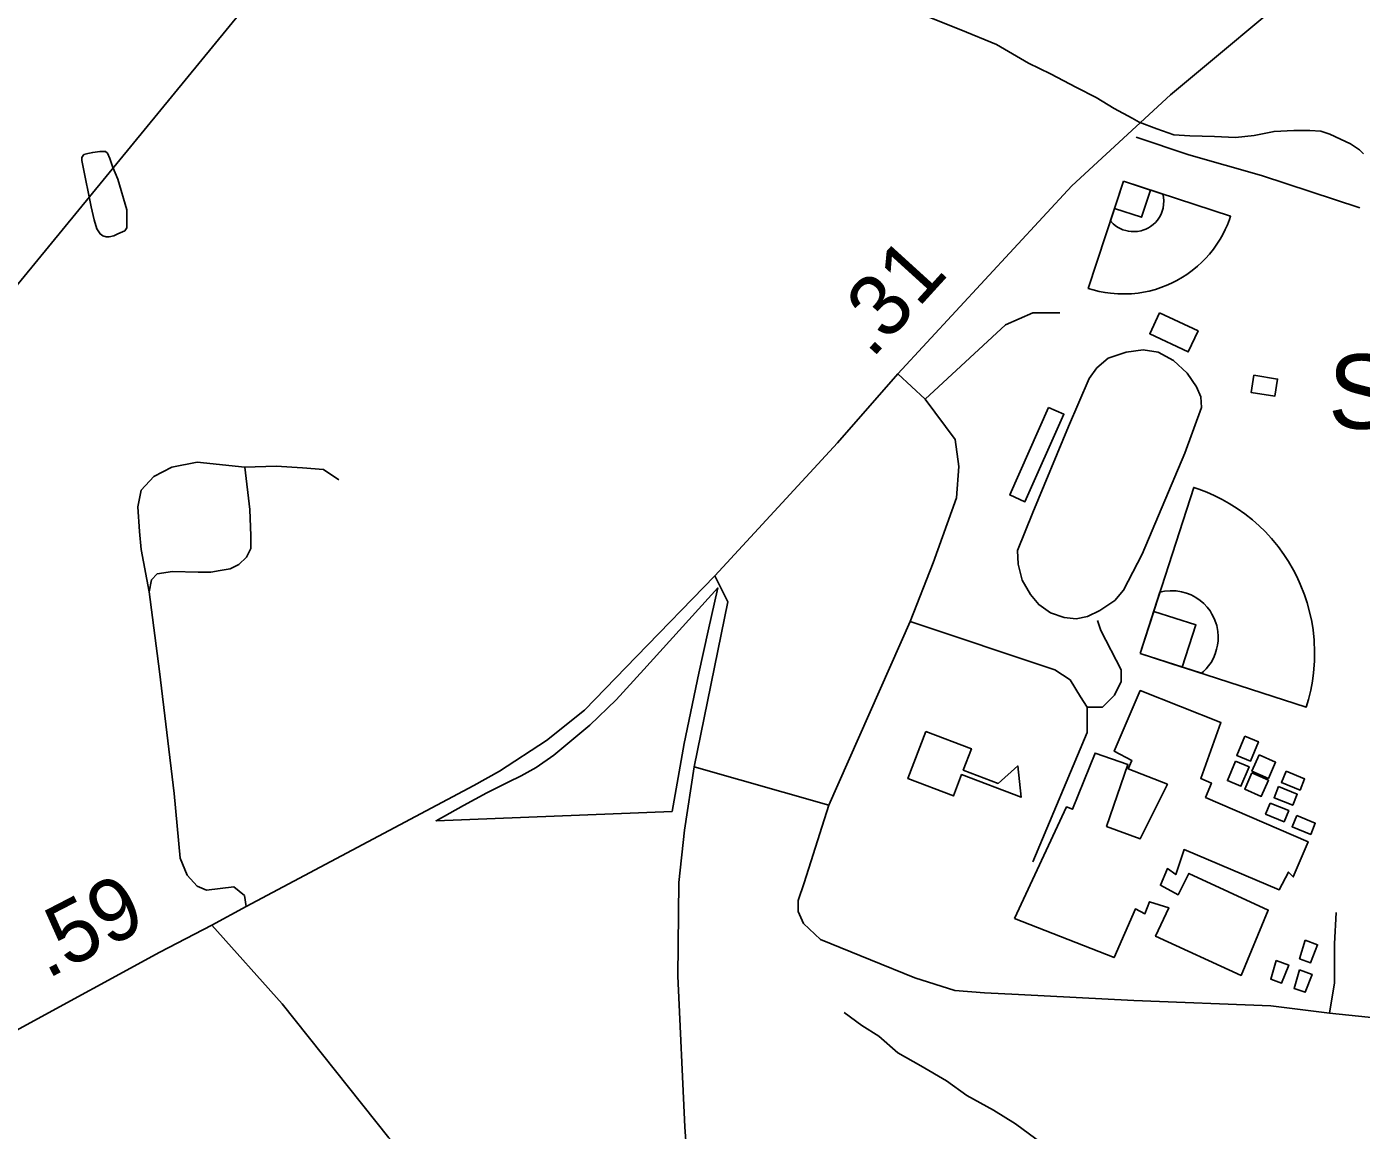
# Model space of a CAD drawing. Extents: x 2082433 to 2279600, y 546599 to 755198.
# Drawn here: x 2146372 to 2149060, y 603647 to 605870 of the extents above; entities that cross this region are included whole.
import ezdxf

# ---------------------------------------------------------------- set-up
doc = ezdxf.new("R2010")
doc.units = 0
for name, color, linetype in [('Exist Boundary Political City Limit New', 7, 'Continuous'), ('Exist Boundary Political Fire Districts', 7, 'Continuous'), ('Exist Cultural Educational Facility High CELL', 7, 'Continuous'), ('Exist Cultural Educational Facility High Footprint', 7, 'Continuous'), ('Exist Cultural Educational Facility High Label', 7, 'Continuous'), ('Exist Cultural Recreational Athletic Track', 7, 'Continuous'), ('Exist Cultural Recreational Baseball or SoftBall Diamond CELL', 7, 'Continuous'), ('Exist Hydrographic Misc Water Feature', 7, 'Continuous'), ('Exist Road Non-System Type 51', 7, 'Continuous'), ('Exist Road Primary US Attributed', 7, 'Continuous'), ('Exist Road Primary US Mileage Hundredths English Label', 7, 'Continuous'), ('Exist Road Secondary Type 51 Attributed', 7, 'Continuous'), ('Map Preparation Boundary City Limit Buffer Line', 7, 'Continuous')]:
    doc.layers.add(name, color=color, linetype=linetype)

msp = doc.modelspace()

# ---------------------------------------------------------------- linework, layer by layer
at = {"layer": 'Exist Boundary Political City Limit New'}
msp.add_lwpolyline([(2147672.5, 604289.3), (2147197, 604270.6), (2147252.2, 604301.3), (2147298.8, 604326.7), (2147341.8, 604348.5), (2147368.5, 604361.1), (2147398.5, 604377.6), (2147433.8, 604402.4), (2147506.8, 604462.9), (2147559.8, 604514.4), (2147615.5, 604575.2), (2147764, 604739.7), (2147744.8, 604653.1), (2147726.2, 604567.7), (2147696.5, 604426.1), (2147672.5, 604289.3)], dxfattribs=at)
at = {"layer": 'Exist Boundary Political Fire Districts'}
msp.add_lwpolyline([(2125185.8, 609236.3), (2127409.2, 608956.3), (2130289.8, 608255.9), (2136376.8, 600637.7), (2139465.5, 602656.7), (2141242.8, 603675.4), (2141795.1, 603915), (2144979.3, 603672.9), (2148226.1, 607636.4), (2150227.4, 608573.5)], dxfattribs=at)
at = {"layer": 'Exist Cultural Educational Facility High CELL'}
msp.add_lwpolyline([(2148183.5, 604450.4), (2148275, 604415.5), (2148258.6, 604372.5), (2148328.7, 604345.7), (2148368.2, 604381), (2148375.2, 604317.7), (2148255.2, 604363.5), (2148238.8, 604320.5), (2148147.3, 604355.5)], close=True, dxfattribs=at)
at = {"layer": 'Exist Cultural Educational Facility High Footprint'}
for points in [[(2148654.1, 605293.9), (2148731.6, 605257.3), (2148711.7, 605215.1), (2148634.2, 605251.7)], [(2148843.7, 605168), (2148891.5, 605160.3), (2148885.9, 605125.8), (2148838.2, 605133.5)], [(2148430.5, 605103.1), (2148352.1, 604926.9), (2148382.7, 604913.2), (2148461.2, 605089.4)], [(2148361.7, 604073.7), (2148466.8, 604298.4), (2148478.7, 604293.7), (2148524, 604406.8), (2148590.2, 604383.7), (2148547.1, 604259), (2148614.9, 604234.3), (2148669.9, 604343.9), (2148591, 604375), (2148598.2, 604391.7), (2148562.4, 604410.8), (2148614.9, 604532.8), (2148777.4, 604468.2), (2148736.8, 604355.8), (2148758.3, 604346.3), (2148746.6, 604317.5), (2148953, 604228.2), (2148923.1, 604157.4), (2148913.6, 604166.9), (2148894.5, 604131.1), (2148703.3, 604212.4), (2148686.6, 604162.1), (2148669.9, 604174.1), (2148655.5, 604140.6), (2148691.4, 604121.5), (2148712.9, 604164.5), (2148873, 604090.4), (2148818, 603958.9), (2148646, 604037.8), (2148672.3, 604095.2), (2148634, 604107.2), (2148624.5, 604083.2), (2148605.4, 604092.8), (2148562.4, 603994.8)], [(2148825.8, 604440.8), (2148809.5, 604401.8), (2148836.8, 604390.5), (2148853, 604429.5)], [(2148806.9, 604390.4), (2148790.7, 604351.4), (2148817.9, 604340.1), (2148834.1, 604379.1)], [(2148854.3, 604403.1), (2148839.9, 604370.6), (2148873.1, 604355.9), (2148887.5, 604388.3)], [(2148840, 604366.7), (2148825.6, 604334.3), (2148858.9, 604319.5), (2148873.3, 604352)], [(2148908.6, 604370.1), (2148946, 604354.8), (2148936.9, 604332.3), (2148899.4, 604347.7)], [(2148893.8, 604339.3), (2148931.2, 604324), (2148922.1, 604301.6), (2148884.6, 604316.9)], [(2148876.5, 604306.2), (2148914, 604290.9), (2148904.8, 604268.5), (2148867.3, 604283.8)], [(2148930.1, 604280.8), (2148967.6, 604265.4), (2148958.4, 604243), (2148920.9, 604258.3)], [(2148947, 604030.1), (2148935.9, 603992.3), (2148958, 603984.5), (2148972.1, 604020.7)], [(2148888.8, 603989.2), (2148877.8, 603951.4), (2148899.8, 603943.5), (2148914, 603979.7)], [(2148935.9, 603970.4), (2148924.9, 603932.7), (2148946.9, 603924.8), (2148961.1, 603961)]]:
    msp.add_lwpolyline(points, close=True, dxfattribs=at)
at = {"layer": 'Exist Cultural Recreational Athletic Track'}
msp.add_lwpolyline([(2148367.7, 604814.9), (2148368.9, 604787.4), (2148377.3, 604755.1), (2148394, 604726.4), (2148410.8, 604706.1), (2148434.6, 604689.4), (2148462.1, 604679.8), (2148486, 604677.4), (2148508.7, 604682.2), (2148533.8, 604694.2), (2148563.7, 604714.5), (2148581.6, 604734.8), (2148618.6, 604807.7), (2148704.6, 605011), (2148738.1, 605103), (2148736.9, 605124.6), (2148728.5, 605144.9), (2148709.4, 605172.4), (2148681.9, 605197.5), (2148650.9, 605214.2), (2148621, 605219), (2148586.4, 605214.2), (2148550.5, 605202.3), (2148527.8, 605183.1), (2148512.3, 605161.6), (2148470.5, 605064.8), (2148398.8, 604891.4)], close=True, dxfattribs=at)
at = {"layer": 'Exist Cultural Recreational Baseball or SoftBall Diamond CELL'}
for points in [[(2148581, 605559), (2148796.9, 605488.3), (2148794.8, 605482), (2148790.6, 605471.2), (2148786.3, 605461.7), (2148781.1, 605451.6), (2148775.9, 605442.3), (2148769.4, 605432.1), (2148762.4, 605422), (2148754.3, 605412), (2148746.5, 605403.3), (2148739.2, 605395.8), (2148730.1, 605387.6), (2148719.6, 605379), (2148709.1, 605371.3), (2148699.9, 605365.4), (2148689, 605359), (2148680.7, 605354.7), (2148670.6, 605350.1), (2148656.7, 605344.7), (2148646, 605341.1), (2148632.9, 605337.7), (2148621.7, 605335.4), (2148610.8, 605333.7), (2148597.4, 605332.2), (2148581.7, 605331.8), (2148570, 605331.9), (2148555, 605333.2), (2148544.1, 605334.7), (2148532.6, 605337), (2148520.1, 605339.9), (2148510.4, 605343)], [(2148581, 605559), (2148660.7, 605533), (2148662.1, 605526.9), (2148662.6, 605519.7), (2148662.2, 605511.7), (2148661.1, 605504.7), (2148659.3, 605498.3), (2148656.9, 605492.5), (2148653.7, 605486.3), (2148649.7, 605480.6), (2148645.6, 605476), (2148641.1, 605471.6), (2148636, 605467.7), (2148631.7, 605465.2), (2148626, 605462.3), (2148620.4, 605460.3), (2148617.2, 605459.2), (2148609.2, 605457.7), (2148603.3, 605457.4), (2148596.9, 605457.4), (2148591.3, 605458.1), (2148586.1, 605459.4), (2148580.1, 605461.3), (2148574.6, 605463.6), (2148569.1, 605466.6), (2148564.8, 605469.8), (2148560.5, 605473.2), (2148557.3, 605476.5), (2148554.9, 605479.3)], [(2148581, 605559), (2148563.1, 605504.2), (2148617.8, 605486.3), (2148635.7, 605541.1)], [(2148614.8, 604607.5), (2148722.9, 604941.9), (2148732.8, 604938.7), (2148749.4, 604932.3), (2148764.2, 604925.7), (2148779.8, 604917.7), (2148794.2, 604909.7), (2148810.1, 604899.6), (2148825.7, 604888.9), (2148841.3, 604876.4), (2148854.8, 604864.4), (2148866.3, 604853.1), (2148879.1, 604839.1), (2148892.5, 604822.9), (2148904.4, 604806.7), (2148913.6, 604792.5), (2148923.6, 604775.6), (2148930.3, 604762.8), (2148937.4, 604747.2), (2148945.9, 604725.8), (2148951.4, 604709.3), (2148956.8, 604689), (2148960.5, 604671.6), (2148963, 604654.8), (2148965.4, 604634.1), (2148966.2, 604609.8), (2148966.1, 604591.7), (2148964.1, 604568.5), (2148961.9, 604551.6), (2148958.4, 604533.8), (2148953.9, 604514.5), (2148949.2, 604499.4)], [(2148614.8, 604607.5), (2148654.6, 604731), (2148664, 604733.1), (2148675.1, 604734), (2148687.5, 604733.5), (2148698.3, 604731.7), (2148708.2, 604728.9), (2148717.3, 604725.4), (2148726.8, 604720.5), (2148735.6, 604714.3), (2148742.8, 604707.9), (2148749.6, 604700.9), (2148755.6, 604693.1), (2148759.5, 604686.5), (2148764.1, 604677.6), (2148767.1, 604669.1), (2148769, 604664.1), (2148771.3, 604651.8), (2148771.8, 604642.6), (2148771.9, 604632.7), (2148770.7, 604624), (2148768.7, 604616), (2148765.9, 604606.7), (2148762.4, 604598.2), (2148757.7, 604589.6), (2148752.8, 604582.9), (2148747.6, 604576.3), (2148742.4, 604571.3), (2148738.1, 604567.5)], [(2148614.8, 604607.5), (2148699.6, 604580.1), (2148727, 604664.9), (2148642.2, 604692.3)]]:
    msp.add_lwpolyline(points, close=True, dxfattribs=at)
at = {"layer": 'Exist Hydrographic Misc Water Feature'}
for points in [[(2148187.6, 605890), (2148253.8, 605864.2), (2148325.8, 605834.6), (2148390.1, 605797), (2148434, 605775.3), (2148486.5, 605747.5), (2148526.5, 605727.6), (2148562.4, 605705.6), (2148598.7, 605685.9), (2148612.6, 605678.1), (2148648.5, 605664.2), (2148682.5, 605652.1), (2148714.7, 605650.5), (2148764.6, 605648.7), (2148806.8, 605646.8), (2148844.3, 605651.2), (2148884.5, 605659.3), (2148924.3, 605661.4), (2148956.7, 605661.4), (2148978.4, 605659.7), (2148996.7, 605653.7), (2149018.2, 605643.6), (2149038.3, 605634), (2149056.8, 605621.9)], [(2149056.8, 605621.9), (2149064.4, 605613.9)], [(2146513.9, 605463), (2146518, 605457.1), (2146520.3, 605452.7), (2146526, 605449), (2146532.2, 605446.9), (2146538.5, 605447.1), (2146548.2, 605448.9), (2146556.2, 605453), (2146569.9, 605459), (2146573.8, 605465.3), (2146574, 605481.1), (2146573.8, 605501), (2146555.7, 605562.9), (2146545.5, 605588.8), (2146539.8, 605604.7), (2146535.4, 605615.1), (2146531.3, 605618.9), (2146527.7, 605618.7), (2146519.5, 605618.7), (2146505.5, 605616.8), (2146495.5, 605614.6), (2146487.5, 605612.6), (2146483.6, 605606.7), (2146483.8, 605600.6), (2146485.4, 605590.6), (2146502.2, 605507), (2146508, 605480.9), (2146513.9, 605463)], [(2148018.8, 603884.2), (2148054.3, 603858.1), (2148088.5, 603836.3), (2148126.7, 603802.6), (2148173, 603776.9), (2148224.9, 603746.7), (2148265.5, 603717.1), (2148319.2, 603687.5), (2148363.5, 603659.7), (2148417.6, 603619.9)]]:
    msp.add_lwpolyline(points, dxfattribs=at)
at = {"layer": 'Exist Road Non-System Type 51'}
for p, q in [((2148182, 605120), (2148126.6, 605170.8)), ((2147988, 604302.1), (2148152, 604671.8)), ((2147988, 604302.1), (2147716.9, 604379.1))]:
    msp.add_line(p, q, dxfattribs=at)
for points in [[(2149057.4, 605505.5), (2148859.1, 605570.5), (2148713, 605611.8), (2148606.9, 605647.4)], [(2148182, 605120), (2148343.7, 605269.8), (2148398.5, 605293.8), (2148453.3, 605293.8)], [(2148152, 604671.8), (2148198.2, 604790.4), (2148245.2, 604921.3), (2148249.8, 604984.4), (2148242.1, 605038.4), (2148182, 605120)], [(2146811.5, 604982.9), (2146715.9, 604993.1), (2146664.6, 604982.9), (2146628.7, 604964.1), (2146603.1, 604936.7), (2146596.2, 604902.6), (2146599.7, 604853), (2146603.1, 604817.1), (2146619.3, 604731.7)], [(2146814.7, 604098), (2146810.8, 604119.6), (2146789.3, 604137.1), (2146734.6, 604130.3), (2146715.9, 604138.8), (2146695.3, 604161), (2146681.7, 604195.2), (2146669.7, 604325.1), (2146639.8, 604571.1), (2146619.3, 604731.7), (2146623.6, 604755.6), (2146635.5, 604767.6), (2146666.3, 604772.7), (2146717.6, 604771), (2146743.2, 604771), (2146762, 604774.4), (2146782.5, 604777.8), (2146799.6, 604786.4), (2146815, 604801.8), (2146823.5, 604818.9), (2146823.5, 604844.5), (2146821.8, 604897.4), (2146811.5, 604982.9)], [(2146811.5, 604982.9), (2146874.8, 604984.6), (2146927.7, 604981.2), (2146970.4, 604977.8), (2147001.2, 604957.2)], [(2148152, 604671.8), (2148443, 604574.7), (2148473.9, 604554.2), (2148494.4, 604520), (2148508.1, 604499.4), (2148508.1, 604448.1), (2148398.5, 604187.8)], [(2148508.1, 604499.4), (2148538.9, 604499.4), (2148562.9, 604523.4), (2148576.6, 604550.8), (2148576.6, 604574.7), (2148535.5, 604653.5), (2148529, 604674)], [(2147988, 604302.1), (2147938.4, 604145.7), (2147926.4, 604109.8), (2147926.4, 604087.6), (2147936.7, 604063.6), (2147970.8, 604031.2), (2148071.6, 603990.2), (2148161.3, 603954.3), (2148241.7, 603928.7), (2148301.5, 603923.5), (2148369.8, 603920.1), (2148602.2, 603908.2), (2148878.1, 603897.9), (2148996, 603882.5)], [(2148996, 603882.5), (2149006.3, 603944), (2149006.3, 604022.6), (2149009.7, 604085.9)], [(2146745.4, 604060.3), (2146886.7, 603901.3), (2147102, 603631.4), (2147151.6, 603581.8)], [(2148996, 603882.5), (2149294.2, 603851.8), (2149595.7, 603814.2), (2149785.4, 603792), (2149834.9, 603774.9), (2149896.5, 603745.8), (2150019.5, 603665.5)]]:
    msp.add_lwpolyline(points, dxfattribs=at)
at = {"layer": 'Exist Road Primary US Attributed'}
for points in [[(2147758.5, 604764.2), (2148005.5, 605031.9), (2148126.6, 605170.8), (2148477.3, 605549.8), (2148676.3, 605733), (2148954.9, 605965.8)], [(2145164.1, 603180.5), (2145339.8, 603282.4), (2145459.2, 603348.7), (2145665.7, 603464.6), (2145887, 603589), (2146364.7, 603855.2), (2146640.6, 604005.6), (2146745.4, 604060.3), (2146814.7, 604098), (2147272.9, 604341.4), (2147324.9, 604370.6), (2147419.6, 604432.3), (2147495.9, 604493.1), (2147600.6, 604601.7), (2147758.5, 604764.2)]]:
    msp.add_lwpolyline(points, dxfattribs=at)
at = {"layer": 'Exist Road Secondary Type 51 Attributed'}
msp.add_lwpolyline([(2147758.5, 604764.2), (2147784.7, 604711.8), (2147716.9, 604379.1), (2147696.9, 604251.3), (2147685.7, 604145.8), (2147684.1, 603957.1), (2147697.6, 603653.6), (2147709.2, 603490.4), (2147715, 603437.2), (2147725.7, 603364.1), (2147744.2, 603277.8), (2147757.7, 603221.6), (2147773.1, 603166.1), (2147817, 603047.5), (2147864, 602939.7), (2147976.8, 602699.4), (2148114.3, 602409.1), (2148210.2, 602234.3), (2148400, 601913.9), (2148557.5, 601633.6)], dxfattribs=at)
at = {"layer": 'Map Preparation Boundary City Limit Buffer Line'}
msp.add_lwpolyline([(2147672.5, 604289.3), (2147197, 604270.6), (2147252.2, 604301.3), (2147298.8, 604326.7), (2147341.8, 604348.5), (2147368.5, 604361.1), (2147398.5, 604377.6), (2147433.8, 604402.4), (2147506.8, 604462.9), (2147559.8, 604514.4), (2147615.5, 604575.2), (2147764, 604739.7), (2147744.8, 604653.1), (2147726.2, 604567.7), (2147696.5, 604426.1), (2147672.5, 604289.3)], dxfattribs=at)

# ---------------------------------------------------------------- texts
at = {"layer": 'Exist Cultural Educational Facility High Label'}
msp.add_text('South Johnston ', height=150, dxfattribs=at).set_placement((2148993.4, 605060.2))
at = {"layer": 'Exist Road Primary US Mileage Hundredths English Label'}
for s, rotation, p in [('.31', 47.7205, (2148074, 605199.1)), ('.59', 27.3887, (2146413.1, 603950.7))]:
    msp.add_text(s, height=125, rotation=rotation, dxfattribs=at).set_placement(p)

doc.saveas('drawing.dxf')
